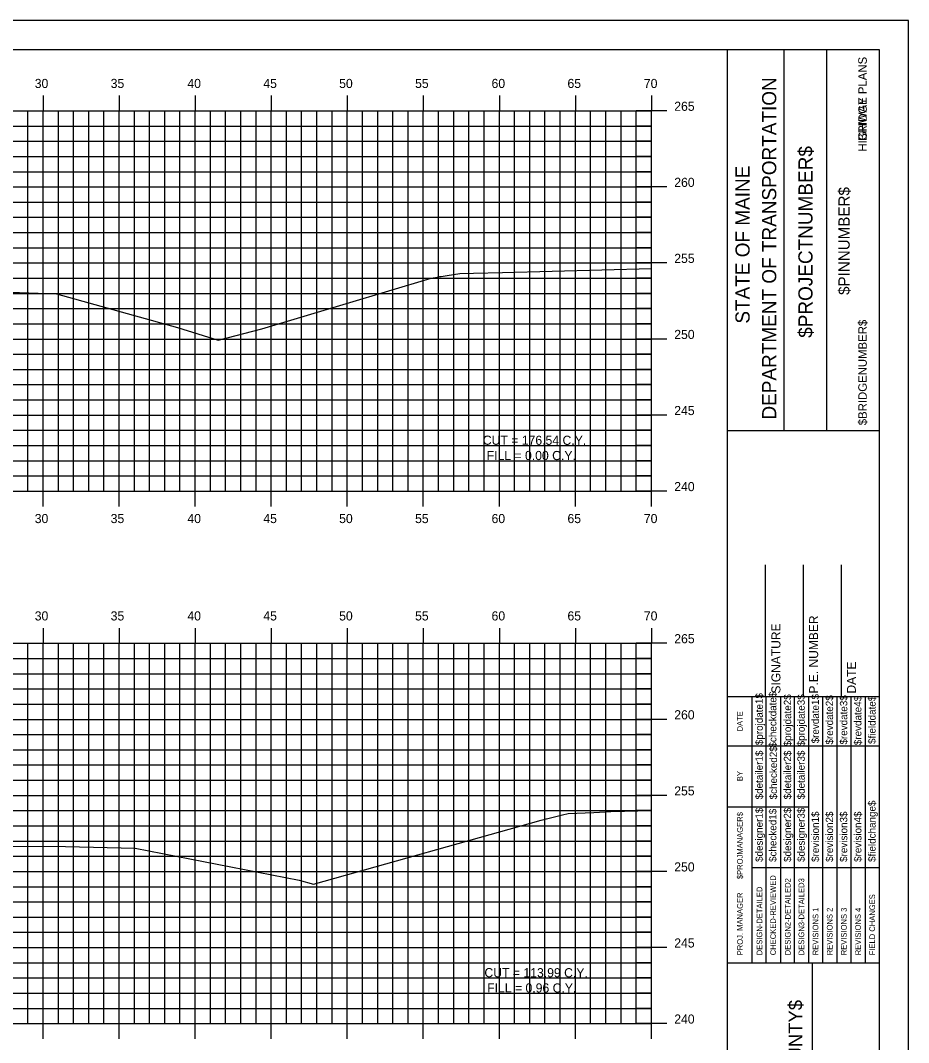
# Model space of a CAD drawing. Extents: x 1160718 to 1173142, y 616002 to 617630.
# Drawn here: x 1170434.4 to 1170492.8, y 616656.7 to 616723.9 of the extents above; entities that cross this region are included whole.
import ezdxf

# ---------------------------------------------------------------- set-up
doc = ezdxf.new("R2010")
doc.units = 0
for name, color, linetype in [('ANNOTATION', 7, 'Continuous'), ('BORDER', 7, 'Continuous'), ('BRIDGE_TITLE', 7, 'Continuous'), ('H_V ANNOTATION', 7, 'Continuous'), ('HIGHWAY_TITLE', 7, 'Continuous'), ('MAJOR', 7, 'Continuous'), ('MINOR', 7, 'Continuous'), ('PLOT BOUNDARY', 7, 'Continuous'), ('S_Roadway_Centerline', 7, 'Continuous')]:
    doc.layers.add(name, color=color, linetype=linetype)

msp = doc.modelspace()

# ---------------------------------------------------------------- linework, layer by layer
at = {"layer": 'BORDER'}
for p, q in [((1170490.907, 616721.928), (1170330.907, 616721.928)), ((1170480.907, 616616.931), (1170480.907, 616721.931)), ((1170484.636, 616696.925), (1170484.636, 616721.925)), ((1170487.431, 616696.925), (1170487.431, 616721.925)), ((1170490.907, 616616.931), (1170490.907, 616721.931)), ((1170480.908, 616696.923), (1170490.907, 616696.923)), ((1170483.407, 616679.431), (1170483.407, 616688.079)), ((1170485.907, 616679.431), (1170485.907, 616688.079)), ((1170488.407, 616679.431), (1170488.407, 616688.079)), ((1170480.907, 616679.431), (1170490.907, 616679.431)), ((1170480.907, 616661.931), (1170490.907, 616661.931)), ((1170486.498, 616626.931), (1170486.498, 616661.931))]:
    msp.add_line(p, q, dxfattribs=at)
for points in [[(1170482.522, 616676.181), (1170482.522, 616679.431)], [(1170483.455, 616661.934), (1170483.455, 616679.431)], [(1170484.386, 616679.431), (1170484.386, 616661.934)], [(1170485.318, 616661.934), (1170485.318, 616679.431)], [(1170486.25, 616661.934), (1170486.25, 616679.431)], [(1170487.181, 616661.934), (1170487.181, 616679.431)], [(1170488.113, 616661.934), (1170488.113, 616679.431)], [(1170489.045, 616661.934), (1170489.045, 616679.431)], [(1170489.977, 616661.934), (1170489.977, 616679.431)], [(1170482.523, 616661.934), (1170482.523, 616678.725)], [(1170480.907, 616676.181), (1170490.907, 616676.181)], [(1170480.907, 616672.181), (1170482.523, 616672.181)], [(1170482.522, 616672.181), (1170486.249, 616672.181)], [(1170482.522, 616668.181), (1170490.907, 616668.181)]]:
    msp.add_lwpolyline(points, dxfattribs=at)
at = {"layer": 'MAJOR'}
for p, q in [((1170435.907, 616718.93), (1170435.907, 616717.928)), ((1170440.907, 616718.93), (1170440.907, 616717.928)), ((1170445.907, 616718.93), (1170445.907, 616717.928)), ((1170450.907, 616718.93), (1170450.907, 616717.928)), ((1170455.907, 616718.93), (1170455.907, 616717.928)), ((1170460.907, 616718.93), (1170460.907, 616717.928)), ((1170465.907, 616718.93), (1170465.907, 616717.928)), ((1170470.907, 616718.93), (1170470.907, 616717.928)), ((1170475.907, 616718.93), (1170475.907, 616717.928)), ((1170335.907, 616717.928), (1170475.907, 616717.928)), ((1170335.907, 616717.928), (1170475.907, 616717.928)), ((1170435.907, 616692.928), (1170435.907, 616717.928)), ((1170440.907, 616692.928), (1170440.907, 616717.928)), ((1170445.907, 616692.928), (1170445.907, 616717.928)), ((1170450.907, 616692.928), (1170450.907, 616717.928)), ((1170455.907, 616692.928), (1170455.907, 616717.928)), ((1170460.907, 616692.928), (1170460.907, 616717.928)), ((1170465.907, 616692.928), (1170465.907, 616717.928)), ((1170470.907, 616692.928), (1170470.907, 616717.928)), ((1170476.909, 616717.928), (1170474.905, 616717.928)), ((1170475.907, 616692.928), (1170475.907, 616717.928)), ((1170475.907, 616692.928), (1170475.907, 616717.928)), ((1170335.907, 616712.928), (1170475.907, 616712.928)), ((1170476.909, 616712.928), (1170474.905, 616712.928)), ((1170335.907, 616707.928), (1170475.907, 616707.928)), ((1170476.909, 616707.928), (1170474.905, 616707.928)), ((1170335.907, 616702.928), (1170475.907, 616702.928)), ((1170476.909, 616702.928), (1170474.905, 616702.928)), ((1170335.907, 616697.928), (1170475.907, 616697.928)), ((1170476.909, 616697.928), (1170474.905, 616697.928)), ((1170335.907, 616692.928), (1170475.907, 616692.928)), ((1170335.907, 616692.928), (1170475.907, 616692.928)), ((1170435.907, 616691.926), (1170435.907, 616692.928)), ((1170440.907, 616691.926), (1170440.907, 616692.928)), ((1170445.907, 616691.926), (1170445.907, 616692.928)), ((1170450.907, 616691.926), (1170450.907, 616692.928)), ((1170455.907, 616691.926), (1170455.907, 616692.928)), ((1170460.907, 616691.926), (1170460.907, 616692.928)), ((1170465.907, 616691.926), (1170465.907, 616692.928)), ((1170470.907, 616691.926), (1170470.907, 616692.928)), ((1170476.909, 616692.928), (1170474.905, 616692.928)), ((1170475.907, 616691.926), (1170475.907, 616692.928)), ((1170435.907, 616683.93), (1170435.907, 616682.928)), ((1170440.907, 616683.93), (1170440.907, 616682.928)), ((1170445.907, 616683.93), (1170445.907, 616682.928)), ((1170450.907, 616683.93), (1170450.907, 616682.928)), ((1170455.907, 616683.93), (1170455.907, 616682.928)), ((1170460.907, 616683.93), (1170460.907, 616682.928)), ((1170465.907, 616683.93), (1170465.907, 616682.928)), ((1170470.907, 616683.93), (1170470.907, 616682.928)), ((1170475.907, 616683.93), (1170475.907, 616682.928)), ((1170335.907, 616682.928), (1170475.907, 616682.928)), ((1170335.907, 616682.928), (1170475.907, 616682.928)), ((1170435.907, 616657.928), (1170435.907, 616682.928)), ((1170440.907, 616657.928), (1170440.907, 616682.928)), ((1170445.907, 616657.928), (1170445.907, 616682.928)), ((1170450.907, 616657.928), (1170450.907, 616682.928)), ((1170455.907, 616657.928), (1170455.907, 616682.928)), ((1170460.907, 616657.928), (1170460.907, 616682.928)), ((1170465.907, 616657.928), (1170465.907, 616682.928)), ((1170470.907, 616657.928), (1170470.907, 616682.928)), ((1170476.909, 616682.928), (1170474.905, 616682.928)), ((1170475.907, 616657.928), (1170475.907, 616682.928)), ((1170475.907, 616657.928), (1170475.907, 616682.928)), ((1170335.907, 616677.928), (1170475.907, 616677.928)), ((1170476.909, 616677.928), (1170474.905, 616677.928)), ((1170335.907, 616672.928), (1170475.907, 616672.928)), ((1170476.909, 616672.928), (1170474.905, 616672.928)), ((1170335.907, 616667.928), (1170475.907, 616667.928)), ((1170476.909, 616667.928), (1170474.905, 616667.928)), ((1170335.907, 616662.928), (1170475.907, 616662.928)), ((1170476.909, 616662.928), (1170474.905, 616662.928)), ((1170335.907, 616657.928), (1170475.907, 616657.928)), ((1170335.907, 616657.928), (1170475.907, 616657.928)), ((1170435.907, 616656.926), (1170435.907, 616657.928)), ((1170440.907, 616656.926), (1170440.907, 616657.928)), ((1170445.907, 616656.926), (1170445.907, 616657.928)), ((1170450.907, 616656.926), (1170450.907, 616657.928)), ((1170455.907, 616656.926), (1170455.907, 616657.928)), ((1170460.907, 616656.926), (1170460.907, 616657.928)), ((1170465.907, 616656.926), (1170465.907, 616657.928)), ((1170470.907, 616656.926), (1170470.907, 616657.928)), ((1170476.909, 616657.928), (1170474.905, 616657.928)), ((1170475.907, 616656.926), (1170475.907, 616657.928))]:
    msp.add_line(p, q, dxfattribs=at)
at = {"layer": 'MINOR'}
for p, q in [((1170434.907, 616692.928), (1170434.907, 616717.928)), ((1170436.907, 616692.928), (1170436.907, 616717.928)), ((1170437.907, 616692.928), (1170437.907, 616717.928)), ((1170438.907, 616692.928), (1170438.907, 616717.928)), ((1170439.907, 616692.928), (1170439.907, 616717.928)), ((1170441.907, 616692.928), (1170441.907, 616717.928)), ((1170442.907, 616692.928), (1170442.907, 616717.928)), ((1170443.907, 616692.928), (1170443.907, 616717.928)), ((1170444.907, 616692.928), (1170444.907, 616717.928)), ((1170446.907, 616692.928), (1170446.907, 616717.928)), ((1170447.907, 616692.928), (1170447.907, 616717.928)), ((1170448.907, 616692.928), (1170448.907, 616717.928)), ((1170449.907, 616692.928), (1170449.907, 616717.928)), ((1170451.907, 616692.928), (1170451.907, 616717.928)), ((1170452.907, 616692.928), (1170452.907, 616717.928)), ((1170453.907, 616692.928), (1170453.907, 616717.928)), ((1170454.907, 616692.928), (1170454.907, 616717.928)), ((1170456.907, 616692.928), (1170456.907, 616717.928)), ((1170457.907, 616692.928), (1170457.907, 616717.928)), ((1170458.907, 616692.928), (1170458.907, 616717.928)), ((1170459.907, 616692.928), (1170459.907, 616717.928)), ((1170461.907, 616692.928), (1170461.907, 616717.928)), ((1170462.907, 616692.928), (1170462.907, 616717.928)), ((1170463.907, 616692.928), (1170463.907, 616717.928)), ((1170464.907, 616692.928), (1170464.907, 616717.928)), ((1170466.907, 616692.928), (1170466.907, 616717.928)), ((1170467.907, 616692.928), (1170467.907, 616717.928)), ((1170468.907, 616692.928), (1170468.907, 616717.928)), ((1170469.907, 616692.928), (1170469.907, 616717.928)), ((1170471.907, 616692.928), (1170471.907, 616717.928)), ((1170472.907, 616692.928), (1170472.907, 616717.928)), ((1170473.907, 616692.928), (1170473.907, 616717.928)), ((1170474.907, 616692.928), (1170474.907, 616717.928)), ((1170335.907, 616716.928), (1170475.907, 616716.928)), ((1170475.907, 616716.928), (1170474.905, 616716.928)), ((1170335.907, 616715.928), (1170475.907, 616715.928)), ((1170475.907, 616715.928), (1170474.905, 616715.928)), ((1170335.907, 616714.928), (1170475.907, 616714.928)), ((1170475.907, 616714.928), (1170474.905, 616714.928)), ((1170335.907, 616713.928), (1170475.907, 616713.928)), ((1170475.907, 616713.928), (1170474.905, 616713.928)), ((1170335.907, 616711.928), (1170475.907, 616711.928)), ((1170475.907, 616711.928), (1170474.905, 616711.928)), ((1170335.907, 616710.928), (1170475.907, 616710.928)), ((1170475.907, 616710.928), (1170474.905, 616710.928)), ((1170335.907, 616709.928), (1170475.907, 616709.928)), ((1170475.907, 616709.928), (1170474.905, 616709.928)), ((1170335.907, 616708.928), (1170475.907, 616708.928)), ((1170475.907, 616708.928), (1170474.905, 616708.928)), ((1170335.907, 616706.928), (1170475.907, 616706.928)), ((1170475.907, 616706.928), (1170474.905, 616706.928)), ((1170335.907, 616705.928), (1170475.907, 616705.928)), ((1170475.907, 616705.928), (1170474.905, 616705.928)), ((1170335.907, 616704.928), (1170475.907, 616704.928)), ((1170475.907, 616704.928), (1170474.905, 616704.928)), ((1170335.907, 616703.928), (1170475.907, 616703.928)), ((1170475.907, 616703.928), (1170474.905, 616703.928)), ((1170335.907, 616701.928), (1170475.907, 616701.928)), ((1170475.907, 616701.928), (1170474.905, 616701.928)), ((1170335.907, 616700.928), (1170475.907, 616700.928)), ((1170475.907, 616700.928), (1170474.905, 616700.928)), ((1170335.907, 616699.928), (1170475.907, 616699.928)), ((1170475.907, 616699.928), (1170474.905, 616699.928)), ((1170335.907, 616698.928), (1170475.907, 616698.928)), ((1170475.907, 616698.928), (1170474.905, 616698.928)), ((1170335.907, 616696.928), (1170475.907, 616696.928)), ((1170475.907, 616696.928), (1170474.905, 616696.928)), ((1170335.907, 616695.928), (1170475.907, 616695.928)), ((1170475.907, 616695.928), (1170474.905, 616695.928)), ((1170335.907, 616694.928), (1170475.907, 616694.928)), ((1170475.907, 616694.928), (1170474.905, 616694.928)), ((1170335.907, 616693.928), (1170475.907, 616693.928)), ((1170475.907, 616693.928), (1170474.905, 616693.928)), ((1170434.907, 616657.928), (1170434.907, 616682.928)), ((1170436.907, 616657.928), (1170436.907, 616682.928)), ((1170437.907, 616657.928), (1170437.907, 616682.928)), ((1170438.907, 616657.928), (1170438.907, 616682.928)), ((1170439.907, 616657.928), (1170439.907, 616682.928)), ((1170441.907, 616657.928), (1170441.907, 616682.928)), ((1170442.907, 616657.928), (1170442.907, 616682.928)), ((1170443.907, 616657.928), (1170443.907, 616682.928)), ((1170444.907, 616657.928), (1170444.907, 616682.928)), ((1170446.907, 616657.928), (1170446.907, 616682.928)), ((1170447.907, 616657.928), (1170447.907, 616682.928)), ((1170448.907, 616657.928), (1170448.907, 616682.928)), ((1170449.907, 616657.928), (1170449.907, 616682.928)), ((1170451.907, 616657.928), (1170451.907, 616682.928)), ((1170452.907, 616657.928), (1170452.907, 616682.928)), ((1170453.907, 616657.928), (1170453.907, 616682.928)), ((1170454.907, 616657.928), (1170454.907, 616682.928)), ((1170456.907, 616657.928), (1170456.907, 616682.928)), ((1170457.907, 616657.928), (1170457.907, 616682.928)), ((1170458.907, 616657.928), (1170458.907, 616682.928)), ((1170459.907, 616657.928), (1170459.907, 616682.928)), ((1170461.907, 616657.928), (1170461.907, 616682.928)), ((1170462.907, 616657.928), (1170462.907, 616682.928)), ((1170463.907, 616657.928), (1170463.907, 616682.928)), ((1170464.907, 616657.928), (1170464.907, 616682.928)), ((1170466.907, 616657.928), (1170466.907, 616682.928)), ((1170467.907, 616657.928), (1170467.907, 616682.928)), ((1170468.907, 616657.928), (1170468.907, 616682.928)), ((1170469.907, 616657.928), (1170469.907, 616682.928)), ((1170471.907, 616657.928), (1170471.907, 616682.928)), ((1170472.907, 616657.928), (1170472.907, 616682.928)), ((1170473.907, 616657.928), (1170473.907, 616682.928)), ((1170474.907, 616657.928), (1170474.907, 616682.928)), ((1170335.907, 616681.928), (1170475.907, 616681.928)), ((1170475.907, 616681.928), (1170474.905, 616681.928)), ((1170335.907, 616680.928), (1170475.907, 616680.928)), ((1170475.907, 616680.928), (1170474.905, 616680.928)), ((1170335.907, 616679.928), (1170475.907, 616679.928)), ((1170475.907, 616679.928), (1170474.905, 616679.928)), ((1170335.907, 616678.928), (1170475.907, 616678.928)), ((1170475.907, 616678.928), (1170474.905, 616678.928)), ((1170335.907, 616676.928), (1170475.907, 616676.928)), ((1170475.907, 616676.928), (1170474.905, 616676.928)), ((1170335.907, 616675.928), (1170475.907, 616675.928)), ((1170475.907, 616675.928), (1170474.905, 616675.928)), ((1170335.907, 616674.928), (1170475.907, 616674.928)), ((1170475.907, 616674.928), (1170474.905, 616674.928)), ((1170335.907, 616673.928), (1170475.907, 616673.928)), ((1170475.907, 616673.928), (1170474.905, 616673.928)), ((1170335.907, 616671.928), (1170475.907, 616671.928)), ((1170475.907, 616671.928), (1170474.905, 616671.928)), ((1170335.907, 616670.928), (1170475.907, 616670.928)), ((1170475.907, 616670.928), (1170474.905, 616670.928)), ((1170335.907, 616669.928), (1170475.907, 616669.928)), ((1170475.907, 616669.928), (1170474.905, 616669.928)), ((1170335.907, 616668.928), (1170475.907, 616668.928)), ((1170475.907, 616668.928), (1170474.905, 616668.928)), ((1170335.907, 616666.928), (1170475.907, 616666.928)), ((1170475.907, 616666.928), (1170474.905, 616666.928)), ((1170335.907, 616665.928), (1170475.907, 616665.928)), ((1170475.907, 616665.928), (1170474.905, 616665.928)), ((1170335.907, 616664.928), (1170475.907, 616664.928)), ((1170475.907, 616664.928), (1170474.905, 616664.928)), ((1170335.907, 616663.928), (1170475.907, 616663.928)), ((1170475.907, 616663.928), (1170474.905, 616663.928)), ((1170335.907, 616661.928), (1170475.907, 616661.928)), ((1170475.907, 616661.928), (1170474.905, 616661.928)), ((1170335.907, 616660.928), (1170475.907, 616660.928)), ((1170475.907, 616660.928), (1170474.905, 616660.928)), ((1170335.907, 616659.928), (1170475.907, 616659.928)), ((1170475.907, 616659.928), (1170474.905, 616659.928)), ((1170335.907, 616658.928), (1170475.907, 616658.928)), ((1170475.907, 616658.928), (1170474.905, 616658.928))]:
    msp.add_line(p, q, dxfattribs=at)
at = {"layer": 'PLOT BOUNDARY'}
msp.add_lwpolyline([(1170322.814, 616613.869), (1170492.814, 616613.869), (1170492.814, 616723.869), (1170322.814, 616723.869)], close=True, dxfattribs=at)
at = {"layer": 'S_Roadway_Centerline'}
for points in [[(1170335.907, 616704.811), (1170340.482, 616705.097), (1170353.832, 616706.596), (1170369.172, 616707.043), (1170383.793, 616706.826), (1170397.533, 616706.967), (1170408.058, 616706.838), (1170431.31, 616706.092), (1170436.791, 616705.902), (1170444.734, 616703.686), (1170447.414, 616702.847), (1170450.297, 616703.605), (1170461.415, 616706.922), (1170461.842, 616707), (1170461.983, 616707.027), (1170462.09, 616707.047), (1170462.469, 616707.105), (1170463.299, 616707.229), (1170464.21, 616707.258), (1170466.107, 616707.306), (1170475.907, 616707.564)], [(1170335.907, 616665.294), (1170355.743, 616667.556), (1170364.533, 616668.511), (1170379.922, 616669.011), (1170393.063, 616669.517), (1170403.588, 616669.541), (1170412.449, 616669.624), (1170437.381, 616669.579), (1170441.967, 616669.453), (1170452.737, 616667.352), (1170453.676, 616667.09), (1170468.662, 616671.302), (1170468.909, 616671.375), (1170468.984, 616671.391), (1170469.014, 616671.396), (1170470.06, 616671.645), (1170470.426, 616671.73), (1170472.115, 616671.808), (1170473.234, 616671.867), (1170475.907, 616671.937)]]:
    msp.add_lwpolyline(points, dxfattribs=at)

# ---------------------------------------------------------------- texts
at = {"layer": 'ANNOTATION'}
for s, p in [('CUT = 176.54 C.Y.', (1170464.818, 616695.978)), ('FILL = 0.00 C.Y.', (1170465.073, 616694.976)), ('CUT = 113.99 C.Y.', (1170464.925, 616660.978)), ('FILL = 0.96 C.Y.', (1170465.105, 616659.976))]:
    msp.add_text(s, height=0.6, rotation=359.92408, dxfattribs=at).set_placement(p)
at = {"layer": 'BORDER'}
for s, height, p in [('DEPARTMENT OF TRANSPORTATION', 0.93176, (1170484.114, 616697.634)), ('$PROJECTNUMBER$', 0.93176, (1170486.499, 616703.008)), ('STATE OF MAINE', 0.93176, (1170482.363, 616703.94)), ('$PINNUMBER$', 0.74527, (1170488.944, 616705.825)), ('SIGNATURE', 0.5906, (1170484.388, 616679.624)), ('P.E. NUMBER', 0.59055, (1170486.868, 616679.624)), ('DATE', 0.5906, (1170489.348, 616679.624)), ('$projdate1$', 0.48455, (1170483.23, 616676.232)), ('$checkdate$', 0.48455, (1170484.125, 616676.074)), ('$projdate2$', 0.48455, (1170485.094, 616676.153)), ('$projdate3$', 0.48455, (1170485.988, 616676.153)), ('$revdate1$', 0.4845, (1170486.92, 616676.35)), ('$revdate2$', 0.4845, (1170487.851, 616676.271)), ('$revdate3$', 0.4845, (1170488.783, 616676.271)), ('$revdate4$', 0.4845, (1170489.715, 616676.232)), ('$fielddate$', 0.48455, (1170490.646, 616676.31)), ('DATE', 0.3714, (1170481.912, 616677.137)), ('$checked2$', 0.4845, (1170484.162, 616672.667)), ('$detailer1$', 0.48455, (1170483.23, 616672.667)), ('$detailer2$', 0.48455, (1170485.094, 616672.667)), ('$detailer3$', 0.48455, (1170485.988, 616672.667)), ('BY', 0.3714, (1170481.912, 616673.866)), ('$designer1$', 0.48455, (1170483.23, 616668.555)), ('$checked1$', 0.4845, (1170484.125, 616668.555)), ('$designer2$', 0.48455, (1170485.094, 616668.555)), ('$designer3$', 0.48455, (1170485.988, 616668.555)), ('$fieldchange$', 0.48455, (1170490.646, 616668.555)), ('$PROJMANAGER$', 0.37275, (1170481.912, 616667.426)), ('$revision1$', 0.48455, (1170486.92, 616668.555)), ('$revision2$', 0.48455, (1170487.851, 616668.555)), ('$revision3$', 0.48455, (1170488.783, 616668.555)), ('$revision4$', 0.48455, (1170489.715, 616668.555)), ('CHECKED-REVIEWED', 0.37275, (1170484.088, 616662.419)), ('DESIGN2-DETAILED2', 0.37275, (1170485.057, 616662.419)), ('DESIGN3-DETAILED3', 0.37275, (1170485.952, 616662.419)), ('DESIGN-DETAILED', 0.37275, (1170483.194, 616662.419)), ('PROJ. MANAGER', 0.37275, (1170481.912, 616662.419)), ('FIELD CHANGES', 0.37275, (1170490.61, 616662.419)), ('REVISIONS 1', 0.37275, (1170486.883, 616662.419)), ('REVISIONS 2', 0.37275, (1170487.815, 616662.419)), ('REVISIONS 3', 0.37275, (1170488.747, 616662.419)), ('REVISIONS 4', 0.37275, (1170489.678, 616662.419))]:
    msp.add_text(s, height=height, rotation=90, dxfattribs=at).set_placement(p)
at = {"layer": 'BRIDGE_TITLE'}
for s, height, p in [('BRIDGE PLANS', 0.55901, (1170490.066, 616715.953)), ('$BRIDGENUMBER$', 0.55901, (1170490.066, 616697.259)), ('$COUNTY$', 0.9072, (1170485.827, 616653.011))]:
    msp.add_text(s, height=height, rotation=90, dxfattribs=at).set_placement(p)
at = {"layer": 'H_V ANNOTATION'}
for s, p in [('30', (1170435.356, 616719.428)), ('35', (1170440.348, 616719.428)), ('40', (1170445.393, 616719.428)), ('45', (1170450.385, 616719.428)), ('50', (1170455.372, 616719.428)), ('55', (1170460.364, 616719.428)), ('60', (1170465.393, 616719.428)), ('65', (1170470.385, 616719.428)), ('70', (1170475.409, 616719.428)), ('265', (1170477.407, 616717.928)), ('260', (1170477.407, 616712.928)), ('255', (1170477.407, 616707.928)), ('250', (1170477.407, 616702.928)), ('245', (1170477.407, 616697.928)), ('240', (1170477.407, 616692.928)), ('30', (1170435.356, 616690.828)), ('35', (1170440.348, 616690.828)), ('40', (1170445.393, 616690.828)), ('45', (1170450.385, 616690.828)), ('50', (1170455.372, 616690.828)), ('55', (1170460.364, 616690.828)), ('60', (1170465.393, 616690.828)), ('65', (1170470.385, 616690.828)), ('70', (1170475.409, 616690.828)), ('30', (1170435.356, 616684.428)), ('35', (1170440.348, 616684.428)), ('40', (1170445.393, 616684.428)), ('45', (1170450.385, 616684.428)), ('50', (1170455.372, 616684.428)), ('55', (1170460.364, 616684.428)), ('60', (1170465.393, 616684.428)), ('65', (1170470.385, 616684.428)), ('70', (1170475.409, 616684.428)), ('265', (1170477.407, 616682.928)), ('260', (1170477.407, 616677.928)), ('255', (1170477.407, 616672.928)), ('250', (1170477.407, 616667.928)), ('245', (1170477.407, 616662.928)), ('240', (1170477.407, 616657.928))]:
    msp.add_text(s, height=0.6, dxfattribs=at).set_placement(p)
at = {"layer": 'HIGHWAY_TITLE'}
msp.add_text('HIGHWAY PLANS', height=0.55901, rotation=90, dxfattribs=at).set_placement((1170490.066, 616715.244))

doc.saveas('drawing.dxf')
